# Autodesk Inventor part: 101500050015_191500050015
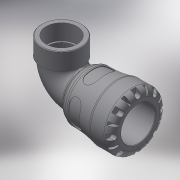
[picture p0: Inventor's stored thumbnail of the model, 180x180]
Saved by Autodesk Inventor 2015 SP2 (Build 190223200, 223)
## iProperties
Created: 2016-12
Part Number: 101500050015_191500050015
Material: Generic
Description: PLASSON 90° ELBOW WITH THREADED FEMALE OFFTAKE 50X1.1/2" SERIES 1
Document SubType Name: Modeling
Designer: KIM
Mass: 557.611 g
Surface Area: 990.043 cm^2
Volume: 557.611 cm^3
Density: 1 g/cm^3
Appearance: Default
Author: KIM
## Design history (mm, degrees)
derived "1015.ipt"
feature "Solid1::1015.ipt"
tag "TaggingFeature1"
body "Solid1"
other parameters: "d1" = 33.18, "d3" = 62.5, "d4" = 85, "d8" = 74.8, "d13" = 9, "d14" = 9, "d15" = 0, "d17" = 360 deg, "d19" = 8 deg, "d20" = 1, "d21" = 1, "d22" = 8 deg, "d24" = 0, "d26" = 360 deg, "d33" = 8.5, "d43" = 69.7, "d51" = 0.85, "d54" = 17.5, "d55" = 11, "d57" = 17.64, "d58" = 0, "d74" = 0, "d78" = 79, "d82" = 1, "d115" = 360 deg, "d207" = 90 deg, "d228" = 14.875, "d247" = 1.7, "d248" = 4.74, "d268" = 41.14, "d269" = 4.74, "d270" = 119, "d279" = 63, "d281" = 6.72675, "d294" = 44.845, "d295" = 24, "d296" = 26.4, "d297" = 40.3605, "d299" = 52.46865, "d300" = 40.3605, "d301" = 0, "d302" = 0, "d303" = 8.61568, "d306" = 0, "d307" = 9, "d308" = 8, "d310" = 3, "E_" = 85, "l_" = 79, "A_" = 119, "A_1" = 63, "l_2" = 24, "Rp_" = 44.845, "d9" = 11.25, "d11" = 85, "d12" = 62.5, "d298" = 58.2985
